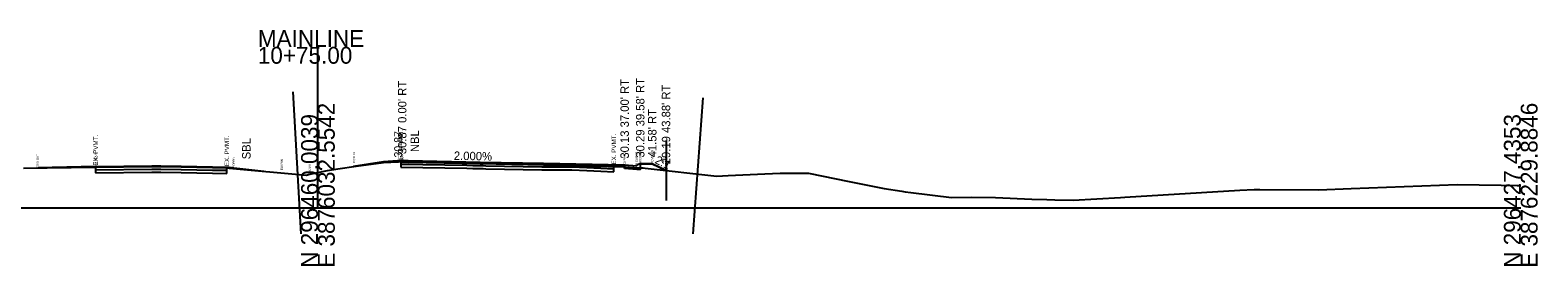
# Model space of a CAD drawing. Extents: x 14823 to 15251, y 114839 to 117377.
# Drawn here: x 15000.5 to 15251.2, y 116338.7 to 116377.9 of the extents above; entities that cross this region are included whole.
import ezdxf

# ---------------------------------------------------------------- set-up
doc = ezdxf.new("R2010")
doc.units = 0
for name, color, linetype in [('Default', 7, 'Continuous'), ('Level 1', 7, 'Continuous'), ('Level 10', 7, 'Continuous'), ('Level 11', 7, 'Continuous'), ('Level 2', 7, 'Continuous'), ('Level 25', 7, 'Continuous'), ('Level 3', 7, 'Continuous'), ('Level 4', 7, 'Continuous'), ('Level 42', 7, 'Continuous'), ('Level 49', 7, 'Continuous'), ('Level 50', 7, 'Continuous'), ('Level 52', 7, 'Continuous'), ('Level 53', 7, 'Continuous'), ('Level 56', 7, 'Continuous'), ('Level 59', 7, 'Continuous'), ('Level 63', 7, 'Continuous')]:
    doc.layers.add(name, color=color, linetype=linetype)

msp = doc.modelspace()

# ---------------------------------------------------------------- linework, layer by layer
at = {"layer": 'Default'}
for p, q in [((15044.21, 116367.65), (15045.54, 116344.04)), ((15112.37, 116366.65), (15110.71, 116344.04))]:
    msp.add_line(p, q, dxfattribs=at)
at = {"layer": 'Level 1'}
for p, q in [((14999.43, 116354.97), (15003.35, 116354.99)), ((15003.35, 116354.99), (15011.39, 116355.09)), ((15011.39, 116355.09), (15020.76, 116355.21)), ((15020.76, 116355.21), (15022.25, 116355.22)), ((15022.25, 116355.22), (15025.6, 116355.16)), ((15025.6, 116355.16), (15030.81, 116355.05)), ((15030.81, 116355.05), (15033.21, 116355)), ((15033.21, 116355), (15033.59, 116354.97)), ((15033.59, 116354.97), (15046.48, 116353.8)), ((15049.97, 116354.58), (15051.66, 116354.86)), ((15051.66, 116354.86), (15054.72, 116355.29)), ((15054.72, 116355.29), (15059.28, 116355.9)), ((15059.28, 116355.9), (15061.76, 116356.02)), ((15061.76, 116356.02), (15062.16, 116356.05)), ((15062.16, 116356.05), (15073.11, 116355.84)), ((15073.11, 116355.84), (15074.12, 116355.82)), ((15074.12, 116355.82), (15075.83, 116355.79)), ((15075.83, 116355.79), (15076.28, 116355.78)), ((15076.28, 116355.78), (15085.61, 116355.59)), ((15085.61, 116355.59), (15089.12, 116355.59)), ((15089.12, 116355.59), (15090.59, 116355.59)), ((15090.59, 116355.59), (15093.1, 116355.47)), ((15093.1, 116355.47), (15095.38, 116355.36)), ((15095.38, 116355.36), (15097.57, 116355.27)), ((15097.57, 116355.27), (15101.65, 116355.03)), ((15101.65, 116355.03), (15102.42, 116354.98)), ((15102.42, 116354.98), (15102.78, 116354.94)), ((15102.78, 116354.94), (15114.7, 116353.6)), ((15046.48, 116353.8), (15046.82, 116353.88)), ((15046.82, 116353.88), (15048.36, 116354.22)), ((15048.36, 116354.22), (15049.97, 116354.58)), ((15114.7, 116353.6), (15116.6, 116353.71)), ((15116.6, 116353.71), (15122.65, 116354.03)), ((15122.65, 116354.03), (15125.2, 116354.1)), ((15125.2, 116354.1), (15126.86, 116354.11)), ((15126.86, 116354.11), (15127.94, 116354.12)), ((15127.94, 116354.12), (15129.92, 116354.1)), ((15129.92, 116354.1), (15136.69, 116352.75)), ((15136.69, 116352.75), (15142.49, 116351.56)), ((15142.49, 116351.56), (15145.46, 116351.12)), ((15145.46, 116351.12), (15146, 116351.03)), ((15146, 116351.03), (15146.93, 116350.92)), ((15146.93, 116350.92), (15153.69, 116350.06)), ((15153.69, 116350.06), (15157.04, 116350.11)), ((15157.04, 116350.11), (15161, 116350.08)), ((15161, 116350.08), (15167.04, 116349.81)), ((15167.04, 116349.81), (15169.56, 116349.71)), ((15173.95, 116349.6), (15181.79, 116350.08)), ((15181.79, 116350.08), (15182.52, 116350.14)), ((15182.52, 116350.14), (15201.64, 116351.26)), ((15201.64, 116351.26), (15204.01, 116351.4)), ((15204.01, 116351.4), (15204.99, 116351.39)), ((15204.99, 116351.39), (15214.8, 116351.36)), ((15214.8, 116351.36), (15220.14, 116351.58)), ((15220.14, 116351.58), (15237.8, 116352.21)), ((15237.8, 116352.21), (15245.13, 116352.12)), ((15245.13, 116352.12), (15247.75, 116352.05)), ((15247.75, 116352.05), (15248.36, 116352.04)), ((15169.56, 116349.71), (15170.91, 116349.67)), ((15170.91, 116349.67), (15173.95, 116349.6))]:
    msp.add_line(p, q, dxfattribs=at)
at = {"layer": 'Level 10'}
for p, q in [((15034.36, 116355.02), (15034.36, 116354.9)), ((15062.37, 116356.11), (15062.37, 116356.23)), ((15062.37, 116355.94), (15062.37, 116356.11)), ((15062.37, 116356.11), (15063.36, 116356.09)), ((15062.37, 116355.94), (15063.36, 116355.92)), ((15075.36, 116355.85), (15063.36, 116356.09)), ((15075.36, 116355.68), (15063.36, 116355.92)), ((15085.86, 116355.64), (15075.36, 116355.85)), ((15085.86, 116355.47), (15075.36, 116355.68)), ((15085.86, 116355.64), (15099.36, 116355.37)), ((15085.86, 116355.47), (15099.36, 116355.2)), ((15099.36, 116355.37), (15099.36, 116355.49)), ((15099.36, 116355.2), (15099.36, 116355.37))]:
    msp.add_line(p, q, dxfattribs=at)
at = {"layer": 'Level 11'}
for p, q in [((15059.26, 116356.02), (15059.26, 116355.9)), ((15099.36, 116354.91), (15099.36, 116355.49)), ((15101.36, 116354.74), (15099.36, 116354.91)), ((15101.95, 116355.66), (15101.95, 116354.74)), ((15101.95, 116354.74), (15101.36, 116354.74))]:
    msp.add_line(p, q, dxfattribs=at)
at = {"layer": 'Level 2'}
for p, q in [((15011.39, 116355.21), (15001.77, 116354.98)), ((15011.39, 116355.21), (15020.76, 116355.33)), ((15020.76, 116355.33), (15022.25, 116355.35)), ((15022.26, 116355.35), (15025.6, 116355.28)), ((15025.6, 116355.28), (15030.82, 116355.18)), ((15030.82, 116355.18), (15033.21, 116355.13)), ((15033.22, 116355.13), (15033.6, 116355.09)), ((15033.6, 116355.09), (15034.36, 116355.02)), ((15062.37, 116356.23), (15059.27, 116356.02)), ((15062.37, 116356.23), (15063.36, 116356.21)), ((15063.36, 116356.21), (15075.36, 116355.97)), ((15075.36, 116355.97), (15085.86, 116355.76)), ((15085.86, 116355.76), (15099.36, 116355.49))]:
    msp.add_line(p, q, dxfattribs=at)
at = {"layer": 'Level 25'}
msp.add_line((15106.24, 116359.55), (15106.24, 116349.55), dxfattribs=at)
at = {"layer": 'Level 3'}
for p, q in [((15034.36, 116355.02), (15039.36, 116354.45)), ((15059.27, 116356.02), (15054.26, 116355.22)), ((15099.36, 116355.49), (15101.36, 116355.33)), ((15101.36, 116355.41), (15101.78, 116355.66)), ((15101.36, 116355.33), (15101.36, 116355.41)), ((15101.78, 116355.66), (15101.95, 116355.66))]:
    msp.add_line(p, q, dxfattribs=at)
at = {"layer": 'Level 4'}
for p, q in [((15101.95, 116355.66), (15103.95, 116355.7)), ((15103.95, 116355.7), (15106.24, 116354.55))]:
    msp.add_line(p, q, dxfattribs=at)
at = {"layer": 'Level 50'}
for points in [[(15062.37, 116356.23), (15063.36, 116356.21), (15075.36, 116355.97), (15085.86, 116355.76), (15099.36, 116355.49), (15099.36, 116355.17), (15097.57, 116355.27), (15095.38, 116355.36), (15093.1, 116355.47), (15090.59, 116355.59), (15089.12, 116355.59), (15085.61, 116355.59), (15076.28, 116355.78), (15075.83, 116355.79), (15074.12, 116355.82), (15073.11, 116355.84), (15062.16, 116356.05), (15061.76, 116356.02), (15059.28, 116355.9), (15054.72, 116355.29), (15054.26, 116355.22), (15059.27, 116356.02)], [(15099.36, 116354.91), (15099.36, 116355.17), (15101.65, 116355.03), (15101.95, 116355.01), (15101.95, 116354.74), (15101.36, 116354.74)], [(15101.95, 116355.66), (15101.95, 116355.01), (15102.42, 116354.98), (15102.78, 116354.94), (15106.24, 116354.55), (15103.95, 116355.7)]]:
    msp.add_lwpolyline(points, close=True, dxfattribs=at)
at = {"layer": 'Level 59'}
for p, q in [((15011.39, 116355.09), (15011.39, 116354.67)), ((15033.21, 116354.59), (15033.21, 116355)), ((15062.16, 116356.05), (15062.16, 116355.63)), ((15062.16, 116355.63), (15073.11, 116355.43)), ((15062.16, 116355.63), (15062.16, 116355.13)), ((15062.16, 116355.13), (15073.11, 116354.93)), ((15073.11, 116355.43), (15074.12, 116355.4)), ((15073.11, 116354.93), (15074.12, 116354.9)), ((15074.12, 116355.4), (15075.83, 116355.37)), ((15074.12, 116354.9), (15075.83, 116354.87)), ((15075.83, 116355.37), (15076.28, 116355.36)), ((15075.83, 116354.87), (15076.28, 116354.86)), ((15076.28, 116355.36), (15085.61, 116355.18)), ((15076.28, 116354.86), (15085.61, 116354.68)), ((15085.61, 116355.18), (15089.12, 116355.18)), ((15089.12, 116355.18), (15090.59, 116355.18)), ((15090.59, 116355.18), (15093.1, 116355.06)), ((15093.1, 116355.06), (15095.38, 116354.95)), ((15095.38, 116354.95), (15097.57, 116354.86)), ((15097.57, 116354.86), (15097.57, 116355.27)), ((15097.57, 116354.86), (15097.57, 116354.86)), ((15097.57, 116354.36), (15097.57, 116354.86)), ((15011.39, 116354.67), (15020.76, 116354.79)), ((15011.39, 116354.67), (15011.39, 116354.67)), ((15011.39, 116354.67), (15011.39, 116354.17)), ((15011.39, 116354.17), (15020.76, 116354.29)), ((15011.39, 116354.17), (15011.39, 116354.17)), ((15020.76, 116354.79), (15022.25, 116354.8)), ((15020.76, 116354.29), (15022.25, 116354.3)), ((15022.25, 116354.8), (15025.6, 116354.74)), ((15022.25, 116354.3), (15025.6, 116354.24)), ((15025.6, 116354.74), (15030.81, 116354.63)), ((15025.6, 116354.24), (15030.81, 116354.13)), ((15030.81, 116354.63), (15033.21, 116354.59)), ((15030.81, 116354.13), (15033.21, 116354.09)), ((15033.21, 116354.09), (15033.21, 116354.59)), ((15085.61, 116354.68), (15089.12, 116354.68)), ((15089.12, 116354.68), (15090.59, 116354.68)), ((15090.59, 116354.68), (15093.1, 116354.56)), ((15093.1, 116354.56), (15095.38, 116354.45)), ((15095.38, 116354.45), (15097.57, 116354.36)), ((15097.57, 116354.36), (15097.57, 116354.36))]:
    msp.add_line(p, q, dxfattribs=at)
at = {"layer": 'Level 63'}
for p, q in [((15048.36, 116348.36), (15048.36, 116375.15)), ((14848.36, 116348.36), (15048.36, 116348.36)), ((15048.36, 116348.36), (15248.36, 116348.36))]:
    msp.add_line(p, q, dxfattribs=at)

# ---------------------------------------------------------------- texts
at = {"layer": 'Level 42'}
for s, p in [('SBL', (15037.16, 116356.42)), ('NBL', (15065.16, 116357.63))]:
    msp.add_text(s, height=1.4, rotation=90, dxfattribs=at).set_placement(p)
at = {"layer": 'Level 49'}
msp.add_text('2.000%', height=1.4, rotation=358.8542, dxfattribs=at).set_placement((15070.95, 116356.34))
at = {"layer": 'Level 50'}
msp.add_text('2:1', height=1.4, rotation=333.435, dxfattribs=at).set_placement((15104.27, 116355.85))
at = {"layer": 'Level 52'}
for s, p in [("30.29 39.58' RT", (15102.65, 116356.71)), ("30.87 0.00' RT", (15063.07, 116357.28)), ("30.13 37.00' RT", (15100.06, 116356.54)), ("29.19 43.88' RT", (15106.94, 116355.6)), ("41.58' RT", (15104.65, 116356.75))]:
    msp.add_text(s, height=1.4, rotation=90, dxfattribs=at).set_placement(p)
at = {"layer": 'Level 53'}
for p in [(15011.77, 116355.09), (15033.59, 116355), (15062.53, 116356.05), (15097.95, 116355.27)]:
    msp.add_text(' EX. PVMT.', height=0.75, rotation=90, dxfattribs=at).set_placement(p)
at = {"layer": 'Level 56'}
for s, p in [('EOPLOUT', (15011.56, 116355.21)), ('EOSLIN', (15054.55, 116355.83)), ('EOPLIN', (15062.55, 116356.23)), ('EOPROUT', (15099.54, 116355.49)), ('FLCURBR', (15101.54, 116355.41)), ('BKCURBR', (15102.12, 116355.66)), ('RCVRBLR', (15104.12, 116355.7)), ('EOSLOUT', (15001.94, 116354.98)), ('EOPRIN', (15034.54, 116355.02)), ('EOSRIN', (15042.54, 116354.62)), ('MEDDIT', (15047.15, 116353.85)), ('FRDTCHR', (15106.42, 116354.55))]:
    msp.add_text(s, height=0.35, rotation=90, dxfattribs=at).set_placement(p)
at = {"layer": 'Level 63'}
for s, p in [('MAINLINE', (15038.37, 116375.15)), ('10+75.00', (15038.36, 116372.35))]:
    msp.add_text(s, height=2.8, dxfattribs=at).set_placement(p)
for s, height, p in [('E 3876032.5542', 2.8, (15051.16, 116338.36)), ('E 3876229.8846', 2.8, (15251.16, 116338.36)), ('N 296460.0039', 2.8, (15048.36, 116338.36)), ('N 296427.4353', 2.8, (15248.36, 116338.36)), (' 30.87', 1.32, (15062.36, 116356.23))]:
    msp.add_text(s, height=height, rotation=90, dxfattribs=at).set_placement(p)

doc.saveas('drawing.dxf')
